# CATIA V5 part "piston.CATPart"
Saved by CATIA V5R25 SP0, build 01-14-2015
Part number: piston
Bounding box of the stored display mesh (mm): x -20 to 20, y -19.998 to 19.998, z 0 to 40
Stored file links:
  C:\Users\feridun\Desktop\teksilindirlimotor\piston.CATPart
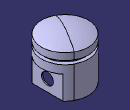
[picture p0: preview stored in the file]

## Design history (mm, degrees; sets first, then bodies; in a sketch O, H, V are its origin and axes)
Body1 (main body)
  Sketch1 on yz-plane, origin (0, 0, 0), H (0, 1, 0), V (0, 0, 1)
    line L1 (0, 0) -> (20, 0)
    line L2 (20, 0) -> (20, 27)
    line L3 (20, 27) -> (17, 27)
    line L4 (17, 27) -> (17, 30)
    line L5 (17, 30) -> (20, 30)
    point P5 (20, 30)
    line L6 (20, 30) -> (20, 35.8258)
    line L7 (0, 0) -> (0, 40)
    arc A1 centre (0, -10) radius 50 from (20, 35.8258) to (0, 40) ccw
    point P8 (0, -10)
    point P9 (17, 37.0213)
    length L1 = 20
    length L7 = 40
    radius A1 = 50
    distance L5 L1 = 30
    length L4 = 3
    length L3 = 3
    horizontal: L1 H, L3 H, L5 H
    vertical: L2 V, L4 V, L6 V, L7 V
    coincidence: P5 L2, A1 P9, P9 L4, P8 V
  Shaft1: profile Sketch1, axis Sketch1.L7, angle 360
  Sketch2 on zx-plane, origin (0, 0, 0), H (-1, 0, 0), V (0, 0, 1)
    line L1 (15, 20) -> (30, 20)
    line L2 (30, 20) -> (30, 0)
    line L3 (30, 0) -> (15, 0)
    line L4 (15, 0) -> (15, 20)
    distance L1 L3 = 20
    distance L2 L4 = 15
    distance L4 V = 15
    horizontal: L1 H, L3 H
    vertical: L2 V, L4 V
    coincidence: L3 H
  Pocket1: profile Sketch2, direction (0, -1, 0), through (limit type 6), opposite side through (limit type 6)
  Mirror1: of Pocket1, about yz-plane
  Sketch3 on face of Pocket1 from Sketch2.L4, origin (-15, 0, 0), H (0, -1, 0), V (0, 0, 1)
    circle A1 centre (0, 10) radius 5
    point P1 (0, 10)
    radius A1 = 5
    distance P1 H = 10
    coincidence: P1 V
  Pocket2: profile Sketch3, direction (1, 0, 0), through (limit type 6)
  Shell1: ExtOffset 0, Face (face of Shaft1 from Sketch1.L1; face of Pocket2 from Sketch3.A1), IntOffset 1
